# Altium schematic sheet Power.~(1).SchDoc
size A4
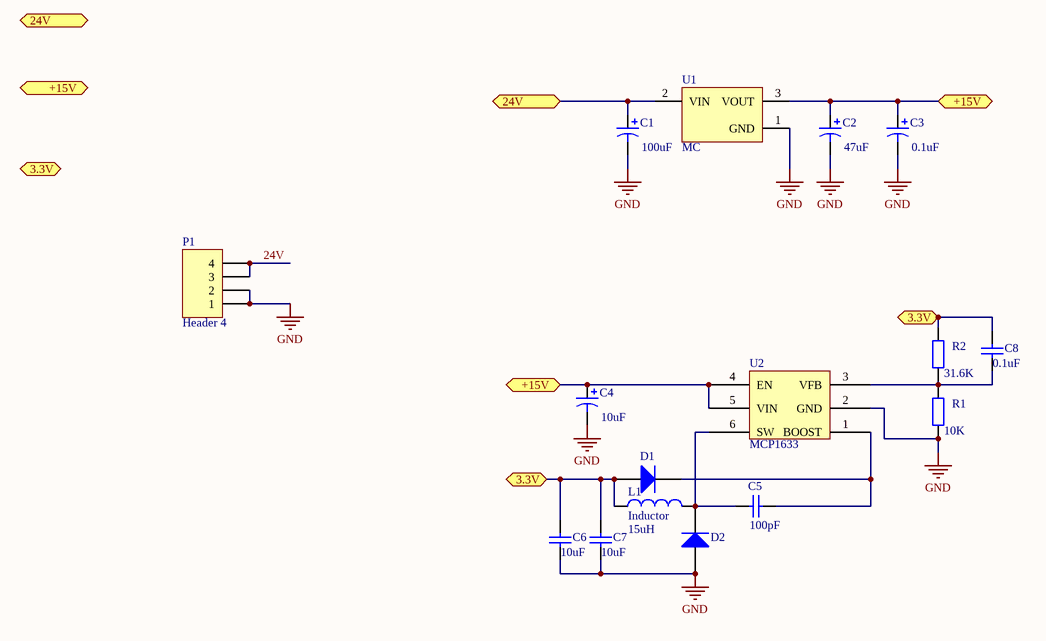
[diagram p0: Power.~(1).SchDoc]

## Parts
C1  value 100uF  [RB7.6-15]
C2  value 47uF  [RB7.6-15]
C3  value 0.1uF  [RB7.6-15]
C4  value 10uF  [RB7.6-15]
C5  value 100pF  [C1206]
C6  value 10uF  [C1206]
C7  value 10uF  [C1206]
C8  value 0.1uF  [C1206]
D1  (no value)  [SMC]
D2  (no value)  [SMC]
L1  Inductor  value 15uH  [INDC3216]
P1  Header 4  [HDR1X4]
R1  value 10K  [AXIAL-0.4]  (hidden comment: Res2)
R2  value 31.6K  [AXIAL-0.4]  (hidden comment: Res2)
U1  MC  [TO-92-TO3]
U2  MCP1633

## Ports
3.3V, 24V, +15V

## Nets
GND: C1.2 C2.2 C3.2 C4.2 C6.2 C7.2 D2.1(A) P1.1 P1.2 R1.1 U1.1(GND) U2.2(GND)
3.3V: C6.1 C7.1 C8.1 D1.1(A) L1.1 R2.2 ; port 3.3V
24V: C1.1 U1.2(VIN) ; port 24V
24V: P1.3 P1.4  [a separate net that carries the same name]
+15V: C2.1 C3.1 C4.1 U1.3(VOUT) U2.4(EN) U2.5(VIN) ; port +15V
NetC5_1: C5.1 D2.2(K) L1.2 U2.6(SW)
NetC5_2: C5.2 D1.2(K) U2.1(BOOST)
NetC8_2: C8.2 R1.2 R2.1 U2.3(VFB)

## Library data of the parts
C1-C4 = Cap Pol1: Polarized Capacitor (Radial)
C5-C8 = Cap Semi: Capacitor (Semiconductor SIM Model)
D1 D2 = Diode: Default Diode
L1 = Inductor: Code_IEC: 1005
P1 = Header 4: Header, 4-Pin
R1 R2 = Res2: Resistor
U1 = MCP1700-1302E/TO: Low Quiescent Current LDO, 3-Pin TO-92, Extended TemperatureBAG; Manufacturer: Microchip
